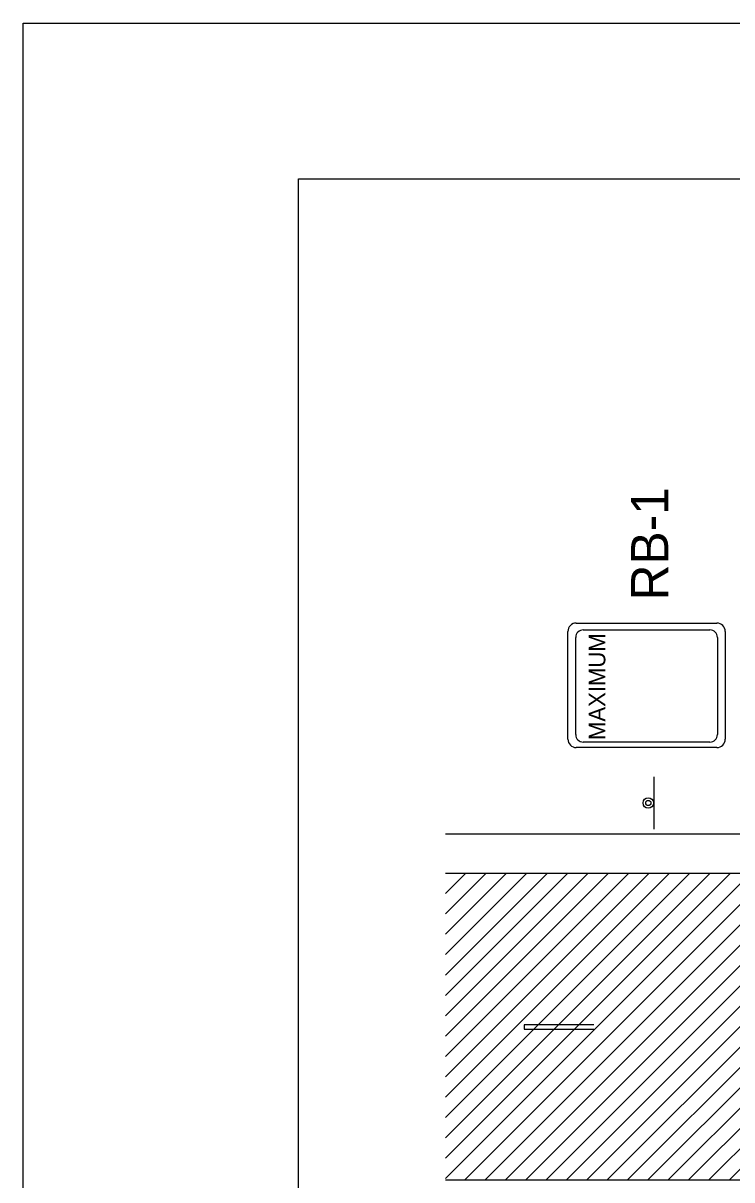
# Model space of a CAD drawing. Extents: x 2111 to 2327, y 208 to 487.
# Drawn here: x 2111.3 to 2160.6, y 406.9 to 487.2 of the extents above; entities that cross this region are included whole.
import ezdxf

# ---------------------------------------------------------------- set-up
doc = ezdxf.new("R2010")
doc.units = 0
for name, color, linetype in [('Level 10', 7, 'Continuous'), ('Level 2', 7, 'Continuous'), ('Level 44', 7, 'Continuous'), ('Level 60', 7, 'Continuous')]:
    doc.layers.add(name, color=color, linetype=linetype)

msp = doc.modelspace()

# ---------------------------------------------------------------- linework, layer by layer
at = {"layer": 'Level 10'}
for p, q in [((2140.664, 430.889), (2199.274, 430.889)), ((2140.664, 428.162), (2199.274, 428.162)), ((2140.664, 428.162), (2140.664, 428.162)), ((2140.664, 426.748), (2142.078, 428.162)), ((2140.664, 425.334), (2143.492, 428.162)), ((2140.664, 423.919), (2144.907, 428.162)), ((2140.664, 422.505), (2146.321, 428.162)), ((2140.664, 421.091), (2147.735, 428.162)), ((2140.664, 419.677), (2149.149, 428.162)), ((2140.664, 418.263), (2150.563, 428.162)), ((2140.664, 416.848), (2151.978, 428.162)), ((2140.664, 415.434), (2153.392, 428.162)), ((2140.664, 414.02), (2154.806, 428.162)), ((2140.664, 412.606), (2156.22, 428.162)), ((2140.664, 411.191), (2157.635, 428.162)), ((2140.664, 409.777), (2159.049, 428.162)), ((2140.664, 408.363), (2160.463, 428.162)), ((2140.664, 406.949), (2161.877, 428.162)), ((2141.991, 406.862), (2163.291, 428.162)), ((2143.406, 406.862), (2164.706, 428.162)), ((2144.82, 406.862), (2166.12, 428.162)), ((2146.234, 406.862), (2167.534, 428.162)), ((2147.649, 406.862), (2168.948, 428.162)), ((2149.063, 406.862), (2170.362, 428.162)), ((2150.477, 406.863), (2171.777, 428.162)), ((2151.892, 406.863), (2173.191, 428.162)), ((2153.306, 406.863), (2174.605, 428.162)), ((2154.72, 406.863), (2176.019, 428.162)), ((2156.134, 406.863), (2177.434, 428.162)), ((2157.549, 406.863), (2178.848, 428.162)), ((2158.963, 406.863), (2180.262, 428.162)), ((2160.377, 406.863), (2181.676, 428.162)), ((2140.664, 406.862), (2199.804, 406.862))]:
    msp.add_line(p, q, dxfattribs=at)
at = {"layer": 'Level 2'}
for p, q in [((2150.967, 417.621), (2146.129, 417.621)), ((2146.129, 417.621), (2146.129, 417.331)), ((2146.129, 417.331), (2150.967, 417.331))]:
    msp.add_line(p, q, dxfattribs=at)
at = {"layer": 'Level 44'}
for p, q in [((2149.742, 445.541), (2159.516, 445.541)), ((2149.164, 437.462), (2149.164, 444.961)), ((2149.702, 437.79), (2149.702, 444.539)), ((2150.224, 445.061), (2159.022, 445.061)), ((2159.544, 444.539), (2159.544, 437.79)), ((2160.098, 444.961), (2160.098, 437.462)), ((2159.022, 437.27), (2150.224, 437.27)), ((2159.024, 437.27), (2159.022, 437.27)), ((2159.516, 436.884), (2149.742, 436.884)), ((2159.52, 436.884), (2159.516, 436.884)), ((2155.152, 431.218), (2155.152, 434.847))]:
    msp.add_line(p, q, dxfattribs=at)
for radius in [0.363, 0.181]:
    msp.add_circle((2154.746, 433.04), radius, dxfattribs=at)
for centre, radius, start, end in [((2149.743, 444.961), 0.579, 89.99999, 179.99999), ((2159.519, 444.961), 0.579, 360, 89.99999), ((2150.226, 444.539), 0.521, 89.99999, 179.99999), ((2159.024, 444.539), 0.521, 360, 89.99999), ((2149.743, 437.463), 0.579, 180, 269.99999), ((2150.226, 437.79), 0.521, 180, 269.99999), ((2159.024, 437.79), 0.521, 270, 359.99999), ((2159.519, 437.463), 0.579, 270, 359.99999)]:
    msp.add_arc(centre, radius, start, end, dxfattribs=at)
at = {"layer": 'Level 60'}
msp.add_line((2111.318, 487.207), (2111.318, 487.207), dxfattribs=at)
for points in [[(2111.318, 487.207), (2327.318, 487.207), (2327.318, 208.207), (2111.318, 208.207)], [(2130.444, 476.398), (2317.318, 476.398), (2317.318, 219.016), (2130.444, 219.016)]]:
    msp.add_lwpolyline(points, close=True, dxfattribs=at)

# ---------------------------------------------------------------- texts
at = {"layer": 'Level 10'}
msp.add_text('RB-1', height=2.5853, rotation=90, dxfattribs=at).set_placement((2156.136, 447.103))
at = {"layer": 'Level 44'}
msp.add_text('MAXIMUM', height=1.1471, rotation=90, dxfattribs=at).set_placement((2151.762, 437.412))

doc.saveas('drawing.dxf')
